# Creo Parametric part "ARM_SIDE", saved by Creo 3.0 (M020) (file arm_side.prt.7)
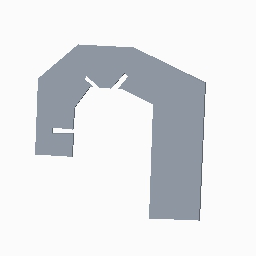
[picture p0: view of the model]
Units: millimeter Newton Second (mmNs); MM, TONNE, SECS

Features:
  1. datum plane "RIGHT"
  2. datum plane "TOP"
  3. datum plane "FRONT"
  4. coordinate system
  5. sketch "Sketch 1"
  6. extrusion "Extrude 1"
  7. sketch "Sketch 2"
  8. sketch "Sketch 3"
  9. extruded cut "Extrude 3"
  10. sketch "Sketch 4"
  11. extruded cut "Extrude 4"
  12. sketch "Sketch 5"
  13. extruded cut "Extrude 5"

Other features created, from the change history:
  datum plane "DTM1"
  sketch "Sketch 2"
  extruded cut "Extrude 2"
  extruded cut "Extrude 3"

Surfaces: 27 plane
